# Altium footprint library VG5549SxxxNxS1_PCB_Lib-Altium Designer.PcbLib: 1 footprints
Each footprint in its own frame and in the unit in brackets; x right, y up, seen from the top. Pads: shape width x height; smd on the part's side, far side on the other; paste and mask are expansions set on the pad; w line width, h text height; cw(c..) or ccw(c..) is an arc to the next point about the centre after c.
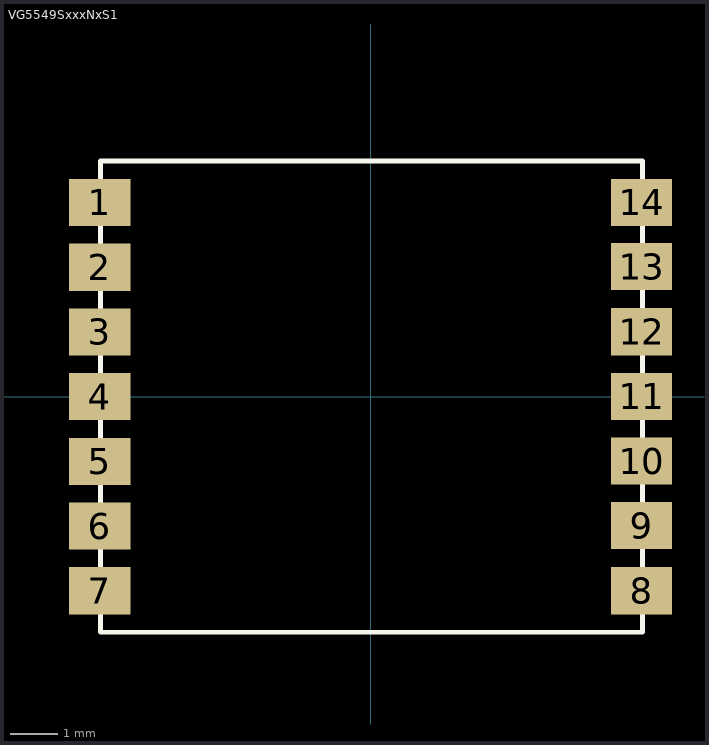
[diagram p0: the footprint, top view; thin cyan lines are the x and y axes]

## VG5549SxxxNxS1 [mm]
pads (15):
  round 1 on Top Overlay: 1(-6.604,5.461)
  rect 1.3x1 smd: 1(-5.75,4.12) 2(-5.75,2.747) 3(-5.75,1.373) 4(-5.75,0) 5(-5.75,-1.373) 6(-5.75,-2.747) 7(-5.75,-4.12) 8(5.75,-4.12) 9(5.75,-2.738) 10(5.75,-1.367) 11(5.75,0.005) 12(5.75,1.377) 13(5.75,2.76) 14(5.75,4.12)
Top Overlay:
  lines w0.1: -5.73,-5 -5.73,5 5.77,5 5.77,-5 -5.73,-5
3D body: height 3.2, standoff -0.1, extent -10.144,-1.296 -10.144,-1.296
